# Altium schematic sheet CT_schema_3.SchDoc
size 283 x 174 mm
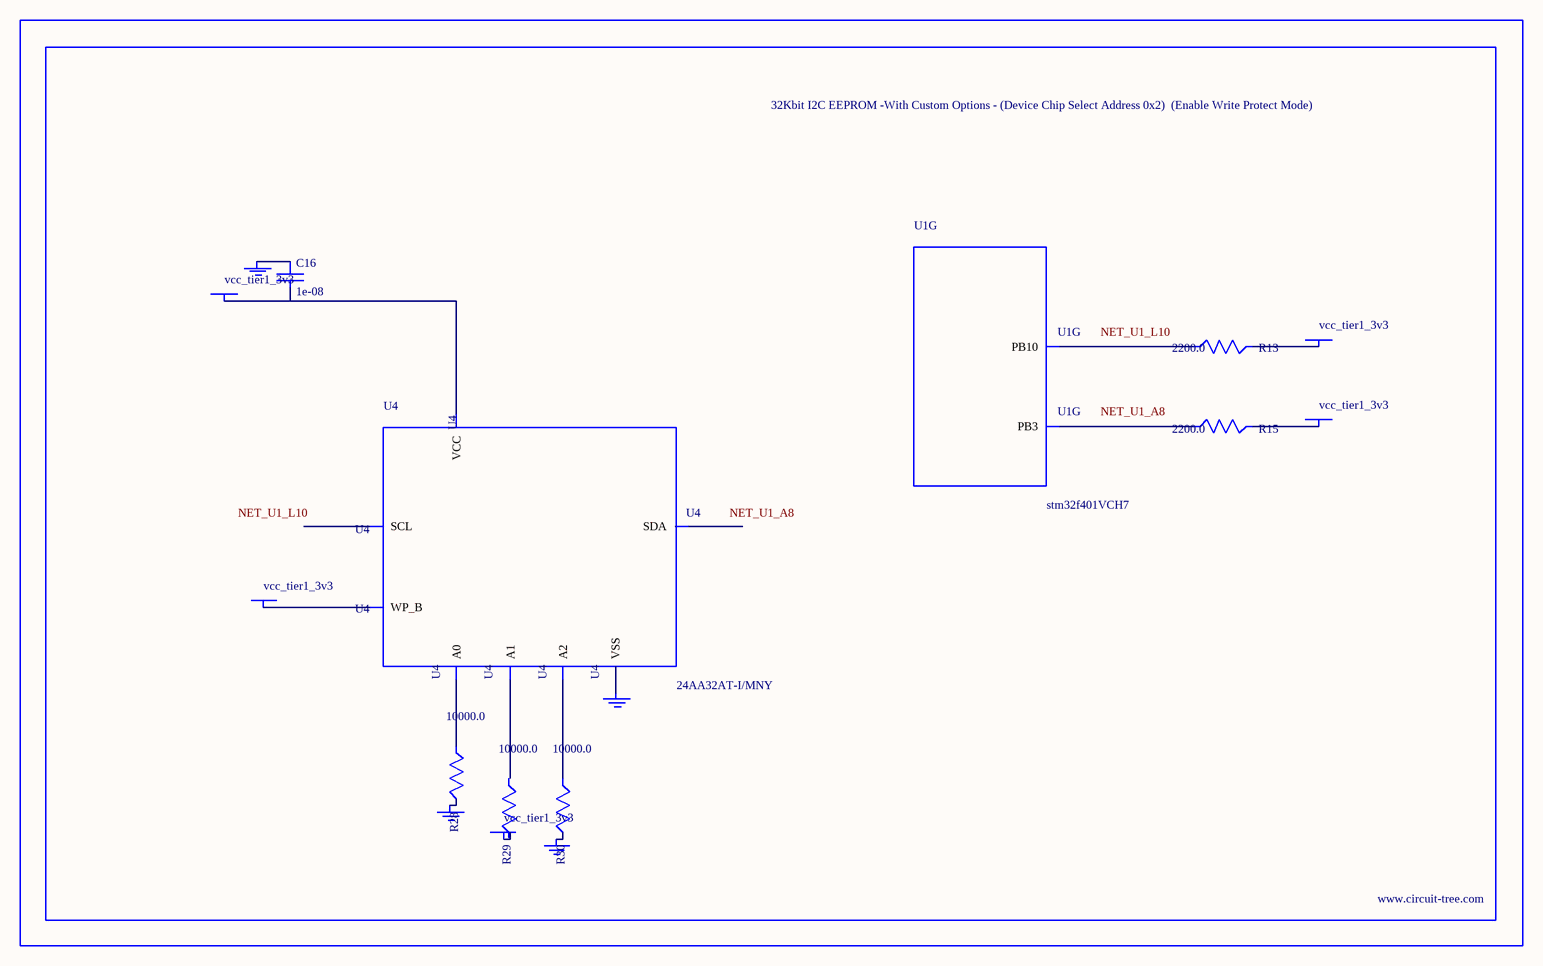
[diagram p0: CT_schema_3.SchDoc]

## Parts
BORDER2  (no value)
C16  1e-08  [C0402]
GND_INSTANCE_2_0  (no value)
GND_INSTANCE_2_1  (no value)
GND_INSTANCE_2_2  (no value)
GND_INSTANCE_2_3  (no value)
POWER_INSTANCE_2_0  vcc_tier1_3v3
POWER_INSTANCE_2_1  vcc_tier1_3v3
POWER_INSTANCE_2_2  vcc_tier1_3v3
POWER_INSTANCE_2_3  vcc_tier1_3v3
POWER_INSTANCE_2_4  vcc_tier1_3v3
R13  2200.0  [R0603]
R15  2200.0  [R0603]
R28  10000.0  [R0603]
R29  10000.0  [R0603]
R30  10000.0  [R0603]
U1  stm32f401VCH7  [UFBGA100]  (part G of 10)
U4  24AA32AT-I/MNY  [TDFN-8/6MM]

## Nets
NetC16_1: C16.1 GND_INSTANCE_2_2.0(GND)
NetC16_2: C16.2 POWER_INSTANCE_2_2.0(PWR) U4.8(VCC)
NetGND_INSTANCE_2_0_0: GND_INSTANCE_2_0.0(GND) R28.2
NetGND_INSTANCE_2_1_0: GND_INSTANCE_2_1.0(GND) R30.2
NetGND_INSTANCE_2_3_0: GND_INSTANCE_2_3.0(GND) U4.4(VSS)
NetPOWER_INSTANCE_2_1_0: POWER_INSTANCE_2_1.0(PWR) U4.7(WP_B)
NetPOWER_INSTANCE_2_3_0: POWER_INSTANCE_2_3.0(PWR) R13.2
NetPOWER_INSTANCE_2_4_0: POWER_INSTANCE_2_4.0(PWR) R15.2
NetR13_1: R13.1 U1.L10(PB10)
NetR15_1: R15.1 U1.A8(PB3)
NetR28_1: R28.1 U4.1(A0)
NetR30_1: R30.1 U4.3(A2)

Not connected (* = marked no-connect by the designer): POWER_INSTANCE_2_0 0(PWR); R29 1 2; U4 2(A1) 5(SDA) 6(SCL)

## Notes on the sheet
- Labels drawn without touching a wire or pin: NET_U1_A8, NET_U1_L10

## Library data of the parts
BORDER2 = BORDER_PAGE2
C16 = C0402C103K3RAC
GND_INSTANCE_2_0-GND_INSTANCE_2_3 = GND
POWER_INSTANCE_2_0-POWER_INSTANCE_2_4 = PWR
R13 R15 = RC0603JR-072K2L
R28-R30 = RC0603JR-0710KL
